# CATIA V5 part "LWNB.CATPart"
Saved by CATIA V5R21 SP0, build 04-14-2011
Part number: LWNB.SLDPRT
Bounding box of the stored display mesh (mm): x -1.375 to 1.375, y -1 to 1, z -0.25 to 0.45
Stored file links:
  C:\Users\user\Desktop\LWNB\LWNB.CATPart
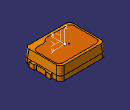
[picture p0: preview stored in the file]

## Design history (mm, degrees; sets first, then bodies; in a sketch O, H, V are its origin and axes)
AxisSystem1: origin (0, 0, 0.45), X (0, -1, 0), Y (1, 0, 0), Z (0, 0, 1)
Set1
  DatumSurface1 to DatumSurface42
  Circle1: stored without definition
  Line1: stored without definition
  Circle2: stored without definition
  Line2: stored without definition
  Circle3: stored without definition
  Line3: stored without definition
  Circle4: stored without definition
  Line4 to Line12: stored without definition
  Circle5: stored without definition
  Line13 to Line27: stored without definition
  Circle6: stored without definition
  Line28: stored without definition
  Circle7: stored without definition
  Line29: stored without definition
  Circle8: stored without definition
  Line30 to Line32: stored without definition
  Circle9: stored without definition
  Line33: stored without definition
  Circle10: stored without definition
  Line34 to Line40: stored without definition
  Circle11: stored without definition
  Line41: stored without definition
  Circle12: stored without definition
  Line42: stored without definition
  Circle13: stored without definition
  Line43: stored without definition
  Circle14: stored without definition
  Line44: stored without definition
  Line45: stored without definition
  Circle15: stored without definition
  Line46: stored without definition
  Circle16: stored without definition
  Line47: stored without definition
  Circle17: stored without definition
  Line48: stored without definition
  Circle18: stored without definition
  Line49: stored without definition
  Circle19: stored without definition
  Line50: stored without definition
  Circle20: stored without definition
  Line51: stored without definition
  Circle21: stored without definition
  Line52: stored without definition
  Circle22: stored without definition
  Line53 to Line56: stored without definition
  Circle23: stored without definition
  Line57 to Line59: stored without definition
  Circle24: stored without definition
  Line60 to Line62: stored without definition
  Circle25: stored without definition
  Line63 to Line65: stored without definition
  Circle26: stored without definition
  Line66 to Line69: stored without definition
  Circle27: stored without definition
  Line70 to Line72: stored without definition
  Circle28: stored without definition
  Line73: stored without definition
  Line74: stored without definition
  Circle29: stored without definition
  Line75 to Line77: stored without definition
  Circle30: stored without definition
  Line78 to Line82: stored without definition
  Circle31: stored without definition
  Line83: stored without definition
  Line84: stored without definition
  Circle32: stored without definition
  Line85 to Line88: stored without definition
  DatumSurface43 to DatumSurface82
  Line89 to Line104: stored without definition
  Circle33: stored without definition
  Line105 to Line122: stored without definition
  Circle34: stored without definition
  Circle35: stored without definition
  Line123: stored without definition
  Circle36: stored without definition
  Line124 to Line127: stored without definition
  Circle37: stored without definition
  Line128: stored without definition
  Circle38: stored without definition
  Line129 to Line135: stored without definition
  Circle39: stored without definition
  Line136: stored without definition
  Circle40: stored without definition
  Line137: stored without definition
  Circle41: stored without definition
  Line138: stored without definition
  Circle42: stored without definition
  Line139: stored without definition
  Line140: stored without definition
  Circle43: stored without definition
  Line141: stored without definition
  Circle44: stored without definition
  Line142: stored without definition
  Circle45: stored without definition
  Line143: stored without definition
  Circle46: stored without definition
  Line144: stored without definition
  Circle47: stored without definition
  Line145: stored without definition
  Circle48: stored without definition
  Line146: stored without definition
  Circle49: stored without definition
  Line147: stored without definition
  Circle50: stored without definition
  Line148: stored without definition
  Circle51: stored without definition
  Line149: stored without definition
  Circle52: stored without definition
  Line150: stored without definition
  Circle53: stored without definition
  Line151: stored without definition
  Circle54: stored without definition
  Line152: stored without definition
  Circle55: stored without definition
  Line153: stored without definition
  Circle56: stored without definition
  Line154: stored without definition
  Circle57: stored without definition
  Line155: stored without definition
  Circle58: stored without definition
  Line156 to Line176: stored without definition
  DatumSurface83 to DatumSurface171
  Line177: stored without definition
  Circle59: stored without definition
  Line178: stored without definition
  Circle60: stored without definition
  Line179: stored without definition
  Circle61: stored without definition
  Line180: stored without definition
  Circle62: stored without definition
  Line181 to Line197: stored without definition
  Circle63: stored without definition
  Line198 to Line214: stored without definition
  Circle64: stored without definition
  Line215: stored without definition
  Circle65: stored without definition
  Line216: stored without definition
  Circle66: stored without definition
  Line217 to Line220: stored without definition
  Circle67: stored without definition
  Circle68: stored without definition
  Line221 to Line227: stored without definition
  Circle69: stored without definition
  Line228: stored without definition
  Circle70: stored without definition
  Line229: stored without definition
  Circle71: stored without definition
  Line230: stored without definition
  Circle72: stored without definition
  Line231 to Line235: stored without definition
  Circle73: stored without definition
  Line236 to Line238: stored without definition
  Circle74: stored without definition
  Line239: stored without definition
  Circle75: stored without definition
  Line240 to Line242: stored without definition
  Circle76: stored without definition
  Line243 to Line249: stored without definition
  Circle77: stored without definition
  Circle78: stored without definition
  Line250 to Line256: stored without definition
  Circle79 to Circle81: stored without definition
  Line257: stored without definition
  Circle82: stored without definition
  Circle83: stored without definition
  Line258: stored without definition
  Circle84: stored without definition
  Line259 to Line266: stored without definition
  Circle85: stored without definition
  Line267 to Line281: stored without definition
  Circle86: stored without definition
  Line282: stored without definition
  Line283: stored without definition
  Circle87: stored without definition
  Line284: stored without definition
  Circle88: stored without definition
  Line285 to Line288: stored without definition
  Circle89: stored without definition
  Circle90: stored without definition
  Line289 to Line295: stored without definition
  Circle91: stored without definition
  Line296: stored without definition
  Circle92: stored without definition
  Line297: stored without definition
  Circle93: stored without definition
  Line298: stored without definition
  Circle94: stored without definition
  Line299 to Line302: stored without definition
  Circle95: stored without definition
  Line303 to Line305: stored without definition
  Circle96: stored without definition
  Line306 to Line309: stored without definition
  Circle97: stored without definition
  Line310: stored without definition
  Circle98: stored without definition
  Line311: stored without definition
  Circle99: stored without definition
  Line312: stored without definition
  Circle100: stored without definition
  Line313 to Line316: stored without definition
  Circle101: stored without definition
  Line317 to Line319: stored without definition
  Circle102: stored without definition
  Line320 to Line325: stored without definition
  Circle103: stored without definition
  Circle104: stored without definition
  Line326 to Line332: stored without definition
  Circle105: stored without definition
  Line333: stored without definition
  DatumCurve1
  Line334: stored without definition
  DatumCurve2
  Line335: stored without definition
  Line336: stored without definition
  DatumCurve3
  Line337: stored without definition
  DatumCurve4
  Line338 to Line340: stored without definition
  Circle106: stored without definition
  Circle107: stored without definition
  Line341: stored without definition
  DatumCurve5
  Line342: stored without definition
  DatumCurve6
  Line343: stored without definition
  Line344: stored without definition
  Circle108: stored without definition
  Line345: stored without definition
  DatumCurve7
  Line346: stored without definition
  DatumCurve8
  Line347 to Line360: stored without definition
  DatumCurve9
  Line361: stored without definition
  DatumCurve10
  Line362: stored without definition
  DatumCurve11
  Line363: stored without definition
  DatumCurve12
  Line364: stored without definition
  DatumCurve13
  Line365: stored without definition
  DatumCurve14
  Line366 to Line370: stored without definition
  DatumCurve15
  Line371: stored without definition
  DatumCurve16
  Line372: stored without definition
  DatumCurve17
  Line373: stored without definition
  DatumCurve18
  Line374: stored without definition
  DatumCurve19
  Line375: stored without definition
  DatumCurve20
  Line376: stored without definition
  Point1 "几何中心（测试原点）": type Between, FirstPoint vertex [face of DatumSurface162], SecondPoint vertex [face of DatumSurface162], Ratio 0.5
  Point2 "虚拟坐标": (0.0061, -0.241, -0.0939), relative to Point1, in AxisSystem1
Body1 (main body)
